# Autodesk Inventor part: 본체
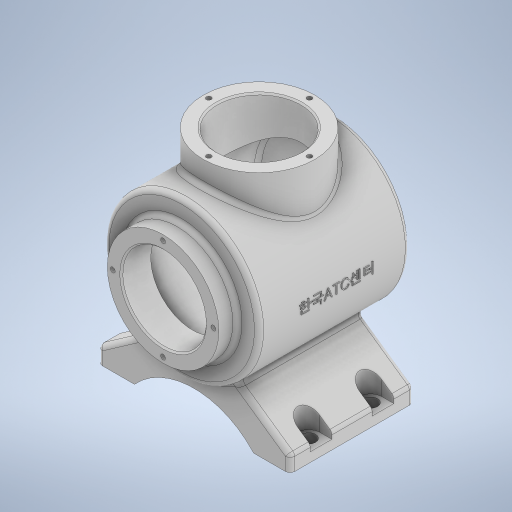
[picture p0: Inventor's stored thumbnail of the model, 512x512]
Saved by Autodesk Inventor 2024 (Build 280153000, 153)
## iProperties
Created: 2023-08
Part Number: 본체
Material: 일반
Document SubType Name: Modeling
Designer: Owner
Density: 1 g/cm^3
Appearance: 기본값
Mass: 480.263 g
Surface Area: 1060.44 cm^2
Volume: 480.263 cm^3
Author: Owner
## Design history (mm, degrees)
sketch "스케치1"
  geometry: L1 (0, 60)-(0, -60); L2 (27, 60)-(36, 60); L3 (36, 60)-(36, 48); L4 (36, 48)-(50, 48); L5 (50, 48)-(50, -48.336); L6 (43, -43.887)-(43, 41); L7 (43, 41)-(27, 41); L8 (27, 41)-(27, 60); A1 r 113 centre (0, 53) between (0, -60) and (50, -48.336); A2 r 106 centre (0, 53) between (0, -53) and (43, -43.887); 3 further points
  constraints: 16 end point, 4 point on circle, 3 perpendicular, 2 centre point, 2 horizontal, 2 midpoint, 2 point on line, 1 coincident, 1 vertical, 1 other
  dimensions: "d0" = 120 distance of L1.start L1.end; "d1" = 113 radius of A1; "d2" = 7 distance between parallel lines of L5 L6; "d3" = 120 vertical distance of L1.end point (31.5, 60); "d4" = 108 vertical distance of L1.end L4.end; "d5" = 7 distance between parallel lines of L4 L7; "d6" = 54 diameter of L8 L1; "d8" = 72 diameter of L3 L1; "d9" = 86 diameter of L6 L1
revolve "회전1" sketch "스케치1" stored, may be unused: angle "d10" = 90 deg
sketch "스케치2"
  geometry: L1 (-26.694, -42.278)-(-62, -67); L2 (-62, -67)-(-62, -77); L3 (-62, -77)-(-38.5, -77); L4 (26.694, -42.278)-(62, -67); L5 (62, -67)-(62, -77); L6 (62, -77)-(38.5, -77); A1 r 50 centre (0, 0) between (-26.694, -42.278) and (26.694, -42.278) reference; A2 r 52.096 centre (0, -112.096) between (38.5, -77) and (-38.5, -77); 4 further points
  constraints: 12 end point, 5 point on circle, 3 equal length, 2 midpoint, 2 perpendicular, 2 vertical, 1 centre point, 1 collinear
  dimensions: "d11" = 55 deg angle of L2 L1; "d12" = 55 deg angle of L4 L5; "d13" = 17 distance from line of L6 point (0, -60); "d14" = 77 distance of L6.end L3.end; "d15" = 10 distance of L4.end L5.end; "d16" = 77 distance from line of L6 point (0, 0); "d17" = 124 distance of point (62, -72) point (-62, -72)
extrude "돌출1" join sketch "스케치2" stored distance "d18" = 80; taper "d19" = 0 deg
node "작업 평면1"
sketch "스케치3"
  geometry: L1 (-36, 60)-(36, 60) reference; C1 r 36 at (0, -2); 1 further point
  constraints: 1 centre point, 1 vertical alignment
  dimensions: "d21" = 72 diameter of C1; "d22" = 62 distance from line of L1 C1.centre
extrude "돌출2" join sketch "스케치3" stored distance "d23" = 80; taper "d24" = 0 deg
sketch "스케치4"
  geometry: C1 r 36 at (0, 0) reference; C2 r 27 at (0, 0); 1 further point
  constraints: 1 centre point, 1 coincident
  dimensions: "d25" = 54 diameter of C2
extrude "돌출3" cut sketch "스케치4" stored distance "d26" = 10; taper "d27" = 0 deg
node "작업 평면2"
sketch "스케치5"
  geometry: L1 (-62, 13)-(-54, 13); L2 (-54, 27)-(-62, 27); L3 (-62, -40)-(-62, 40) reference; L4 (-38.5, 40)-(-62, 40) reference; A1 r 7 centre (-54, 20) between (-54, 13) and (-54, 27); 1 further point
  constraints: 4 end point, 2 point on circle, 2 point on line, 2 tangent, 1 centre point, 1 horizontal, 1 parallel
  dimensions: "d29" = 14 distance between parallel lines of L2 L1; "d30" = 8 distance from line of L3 A1.centre; "d31" = 20 distance from line of L4 A1.centre
extrude "돌출4" cut sketch "스케치5" stored distance "d32" = 10; taper "d33" = 0 deg
sketch "스케치6"
  geometry: C1 r 4.5 at (54, -20); A1 r 7 centre (54, -20) between (54, -13) and (54, -27) reference; 1 further point
  constraints: 1 centre point, 1 coincident
  dimensions: "d34" = 9 diameter of C1
extrude "돌출5" cut sketch "스케치6" extent not by distance; stored distance "d35" = 0; taper "d36" = 0 deg
fillet "모깎기1" dims "d37" = 3
fillet "모깎기2" dims "d38" = 3
chamfer "모따기1" distance "d39" = 1; stored, may be unused: second distance "d40" = 2, angle "d41" = 45 deg
sketch "스케치7"
  geometry: 2 further points
  constraints: 1 vertical alignment
  dimensions: "d42" = 32.5 distance of point (0, 0) point (0, 32.5)
hole "구멍1" sketch "스케치7" at (0, 32.5) diameter "d43" = 3.242; stored, may be unused: countersink angle "d47" = 90 deg, drill point angle "d49" = 118 deg; dims "d44" = 8, "d45" = 4, "d46" = 2, "d48" = 10
sketch "스케치8"
  geometry: C1 r 28 at (0, 0) reference; 2 further points
  constraints: 1 vertical alignment
  dimensions: "d53" = 32.5 distance of C1.centre point (0, 32.5)
hole "구멍2" sketch "스케치8" at (0, 32.5) diameter "d54" = 3.242; stored, may be unused: countersink angle "d58" = 90 deg, drill point angle "d60" = 118 deg; dims "d55" = 8, "d56" = 4, "d57" = 2, "d59" = 10
node "작업 평면3"
sketch "스케치9"
  geometry: L1 (-36, 60.168)-(36, 60.168) reference; 2 further points
  constraints: 1 vertical alignment, 1 other
  dimensions: "d64" = 62 distance from line of L1 point (0, -1.832)
feature "엠보싱1" sketch "스케치9" dims "d0" = 120, "d1" = 113, "d2" = 7, "d3" = 120, "d4" = 108, "d5" = 7, "d6" = 54, "d8" = 72, "d9" = 86, "d11" = 55 deg, "d12" = 55 deg, "d13" = 17, "d14" = 77, "d15" = 10, "d16" = 77, "d17" = 124, "d65" = 0.5, "d66" = 0
node "솔리드1"
mirror "미러1"
mirror "미러2"
mirror "미러3"
mirror "미러4"
pattern_circular "원형 패턴1" dims angle "d51" = 360 deg
pattern_circular "원형 패턴2" dims angle "d62" = 360 deg
feature "A9D066F2-1C7D-4E18-AEED-F7BC21143FA4" dims "d43" = 3.242, "d44" = 8, "d45" = 4, "d46" = 2, "d47" = 90 deg, "d48" = 10, "d49" = 118 deg
other parameters: "d20" = 65, "d28" = -71
